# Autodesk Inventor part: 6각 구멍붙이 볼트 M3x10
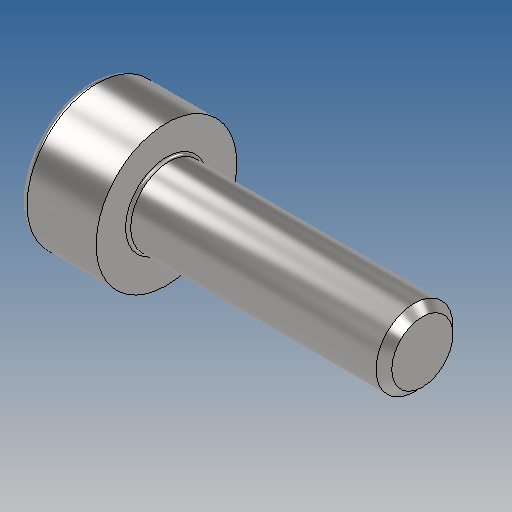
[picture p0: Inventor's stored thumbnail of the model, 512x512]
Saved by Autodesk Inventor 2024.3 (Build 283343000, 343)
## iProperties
Created: 2025-06
Part Number: 6각 구멍붙이 볼트 M3x10
Material: 강철, 연강
Description: 6각머리 태핑 나사
Document SubType Name: Modeling
Designer: user
Density: 7.85 g/cm^3
Appearance: 기본값
Author: jhkim
Sending System: Autodesk Inventor 2026
Preprocessor: ST-DEVELOPER v20.1
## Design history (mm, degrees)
node "6각 구멍붙이 볼트 M3x101"
node "솔리드1"
body "Solid1"
